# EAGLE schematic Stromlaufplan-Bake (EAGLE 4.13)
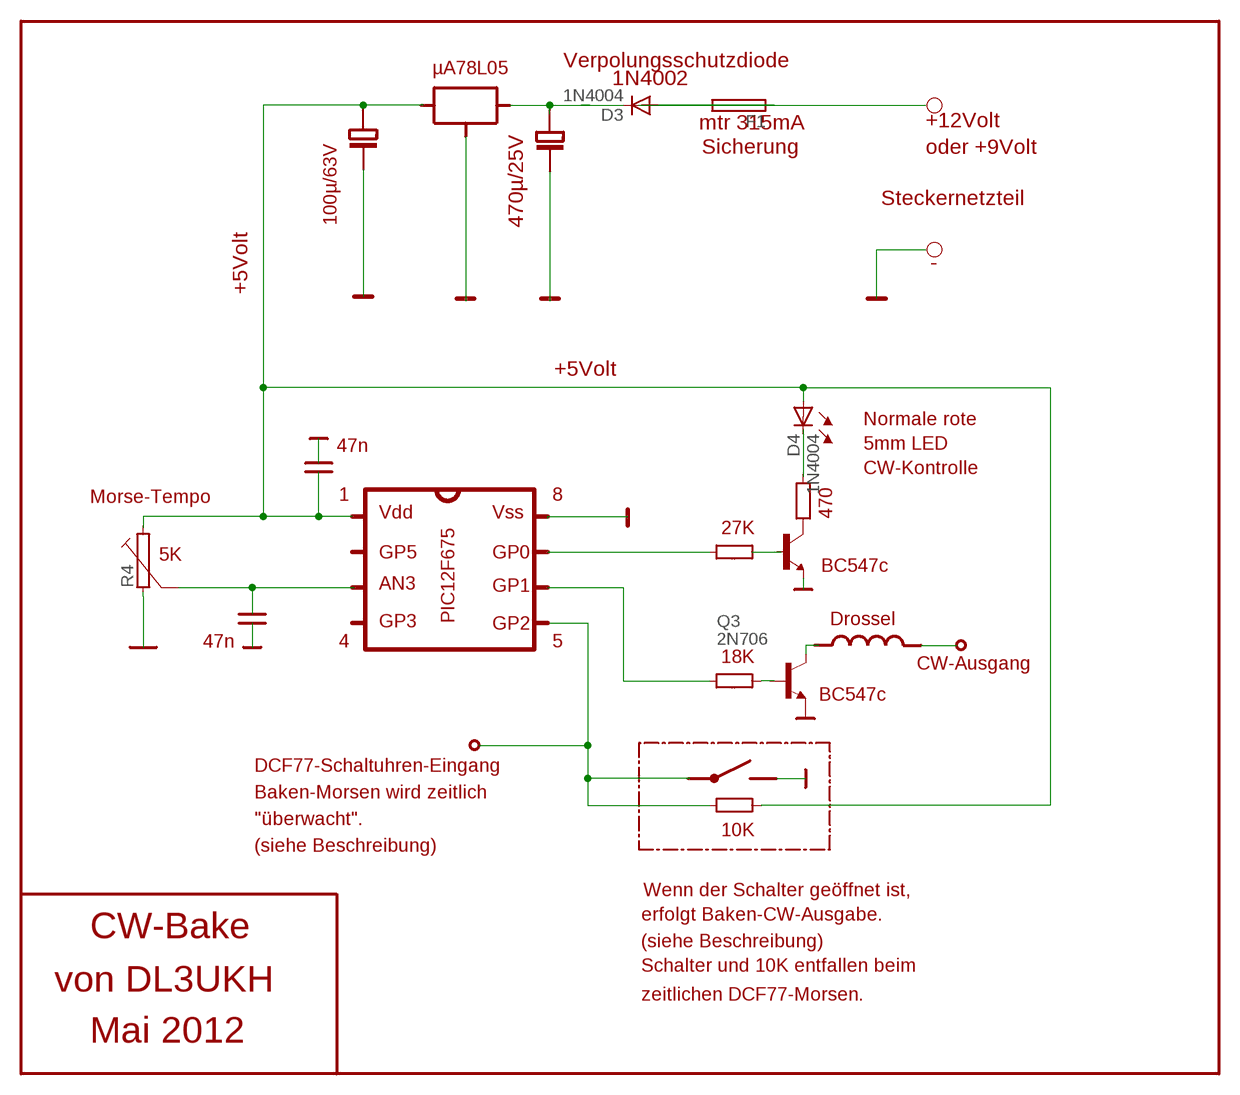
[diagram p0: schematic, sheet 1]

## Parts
D3  1N4004  [DO41-10]
D4  1N4004  [DO41-10]
F1  19559  [19559]
Q3  2N706  [TO18]
R4  RHS10  [HS10]

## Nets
N$1: D4.A R4.2
N$22: D4.C
N$34: Q3.2(B)
N$35: D3.C
N$37: Q3.3(C)
N$47: D3.A F1.1 F1.2
N$72: R4.1
Unconnected: Q3.1(E)

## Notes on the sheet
- Verpolungsschutzdiode
- µA78L05
- 1N4002
- mtr 315mA | +12Volt
- Sicherung
- oder +9Volt
- Steckernetzteil
- 100µ/63V | 470µ/25V
- -
- +5Volt
- +5Volt
- Normale rote
- 47n | 5mm LED
- CW-Kontrolle
- Morse-Tempo | 1 | 8
- Vdd | Vss | 470
- 27K
- 5K | GP5 | GP0
- BC547c
- AN3 | GP1
- GP3 | PIC12F675 | Drossel
- 47n | GP2
- 4 | 5
- 18K
- CW-Ausgang
- BC547c
- DCF77-Schaltuhren-Eingang
- Baken-Morsen wird zeitlich
- "überwacht".
- 10K
- (siehe Beschreibung)
- Wenn der Schalter geöffnet ist,
- erfolgt Baken-CW-Ausgabe.
- CW-Bake
- (siehe Beschreibung)
- Schalter und 10K entfallen beim
- von DL3UKH
- zeitlichen DCF77-Morsen.
- Mai 2012

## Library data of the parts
D3 D4 = diode:1N4004: DIODE
F1 = fuse:19559: FUSE HOLDER
Q3 = transistor-npn:2N706: NPN Transistor
R4 = resistor-power:R: Power Resitor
